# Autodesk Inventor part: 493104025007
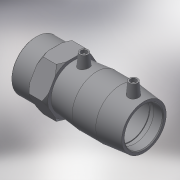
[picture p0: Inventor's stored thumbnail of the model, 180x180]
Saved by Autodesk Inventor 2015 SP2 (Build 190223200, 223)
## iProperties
Created: 2017-06
Part Number: 493104025007
Material: Generic
Description: PLASSON FEMALE TRANSITION COUPLER 25-3/4"
Document SubType Name: Modeling
Designer: KIM
Mass: 67.4103 g
Surface Area: 239.181 cm^2
Volume: 67.4103 cm^3
Density: 1 g/cm^3
Appearance: Default
Author: KIM
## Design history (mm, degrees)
derived "493104.ipt"
feature "Solid1::493104.ipt"
tag "TaggingFeature1"
body "Solid1"
other parameters: "d0" = 82, "d1" = 25, "d2" = 36, "d4" = 27.33333, "d5" = 32.4, "d6" = 23.75, "d7" = 25, "d8" = 168 deg, "d10" = 16, "d11" = 5.33333, "d29" = 38, "d30" = 14, "d31" = 28.7, "d34" = 5 deg, "d41" = 4, "d42" = 14, "d43" = 0, "d48" = 3, "d49" = 0, "d55" = 23, "d57" = 19, "d59" = 24.117, "d60" = 20.7, "d70" = 36, "d71" = 11.5, "d72" = 0, "d73" = 45 deg, "d74" = 1.9, "d75" = 45 deg, "d77" = 0.375, "d80" = 0.5, "d_" = 25, "L_" = 105, "D_1" = 36, "A_" = 38, "d_2" = 12, "L_2" = 23, "D_" = 19, "R_p" = 24.117
